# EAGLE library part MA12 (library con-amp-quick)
AMP QUICK CONNECTOR
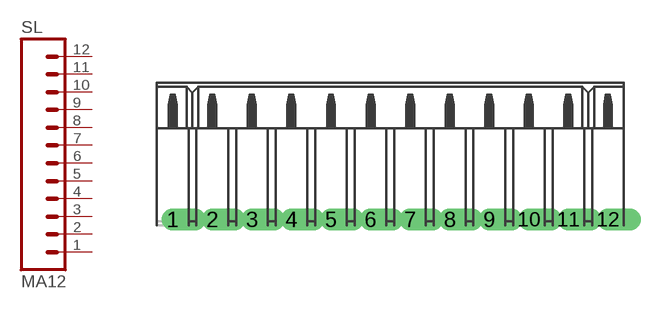
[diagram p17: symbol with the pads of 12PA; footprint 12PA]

Designator prefix SL

## MA12  [12PA]
1  1  pas
2  2  pas
3  3  pas
4  4  pas
5  5  pas
6  6  pas
7  7  pas
8  8  pas
9  9  pas
10  10  pas
11  11  pas
12  12  pas

## Footprint 12PA (pad centres in mm)
AMP QUICK CONNECTOR
drill 0.914 offset: 1 -13.97,0; 2 -11.43,0; 3 -8.89,0; 4 -6.35,0; 5 -3.81,0; 6 -1.27,0; 7 1.27,0; 8 3.81,0; 9 6.35,0; 10 8.89,0; 11 11.43,0; 12 13.97,0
